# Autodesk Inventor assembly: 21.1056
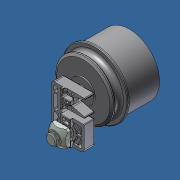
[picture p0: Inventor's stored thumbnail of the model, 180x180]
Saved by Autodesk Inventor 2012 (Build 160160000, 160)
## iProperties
Created: 2007-07
Part Number: 21.1056
Document SubType Name: Assembly
Designer: Andy Moles
Description: BEARING ASSEMBLY FOR TRANSPORT ROLLERS
Vendor: S
Mass: 109.377 g
Surface Area: 170.623 cm^2
Volume: 62.3978 cm^3
Density: 1.7529 g/cm^3
Author: Andy Moles
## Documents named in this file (4)
- Y:\INVENTOR LIBRARIES\PARTS LIBRARY\BELT AND ROLLER CONVEYORS\21.1056 BEARING ASSEMBLY FOR TRANSPORT ROLLERS.iam
- Y:\INVENTOR LIBRARIES\PARTS LIBRARY\BELT AND ROLLER CONVEYORS\SUBCOMPONENTS\21.1056 BEARING ASSEMBLY FOR TRANSPORT ROLLERS PULLEY.ipt
- Y:\INVENTOR LIBRARIES\PARTS LIBRARY\BELT AND ROLLER CONVEYORS\SUBCOMPONENTS\21.1056 BEARING ASSEMBLY FOR TRANSPORT ROLLERS DOWEL.ipt
- Y:\INVENTOR LIBRARIES\PARTS LIBRARY\BELT AND ROLLER CONVEYORS\22.1190 PULLEY CARRIER 36.iam
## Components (3 placed, 3 different names)
1. 21.1056 BEARING ASSEMBLY FOR TRANSPORT ROLLERS PULLEY:1 — Mate:1, Insert:1, Mate:5
2. 21.1056 BEARING ASSEMBLY FOR TRANSPORT ROLLERS DOWEL:1 — Mate:1, Insert:1, Mate:4
3. 22.1190 PULLEY CARRIER 36:1 [sub-assembly] — Mate:4, Mate:5, Angle:1
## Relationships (5: Mate 3, Insert 1, Angle 1)
- Mate:1: 21.1056 BEARING ASSEMBLY FOR TRANSPORT ROLLERS PULLEY:1 ↔ 21.1056 BEARING ASSEMBLY FOR TRANSPORT ROLLERS DOWEL:1
- Insert:1: 21.1056 BEARING ASSEMBLY FOR TRANSPORT ROLLERS PULLEY:1 ↔ 21.1056 BEARING ASSEMBLY FOR TRANSPORT ROLLERS DOWEL:1
- Mate:4: 21.1056 BEARING ASSEMBLY FOR TRANSPORT ROLLERS DOWEL:1 ↔ 22.1190 PULLEY CARRIER 36:1
- Mate:5: 21.1056 BEARING ASSEMBLY FOR TRANSPORT ROLLERS PULLEY:1 ↔ 22.1190 PULLEY CARRIER 36:1
- Angle:1: 22.1190 PULLEY CARRIER 36:1
